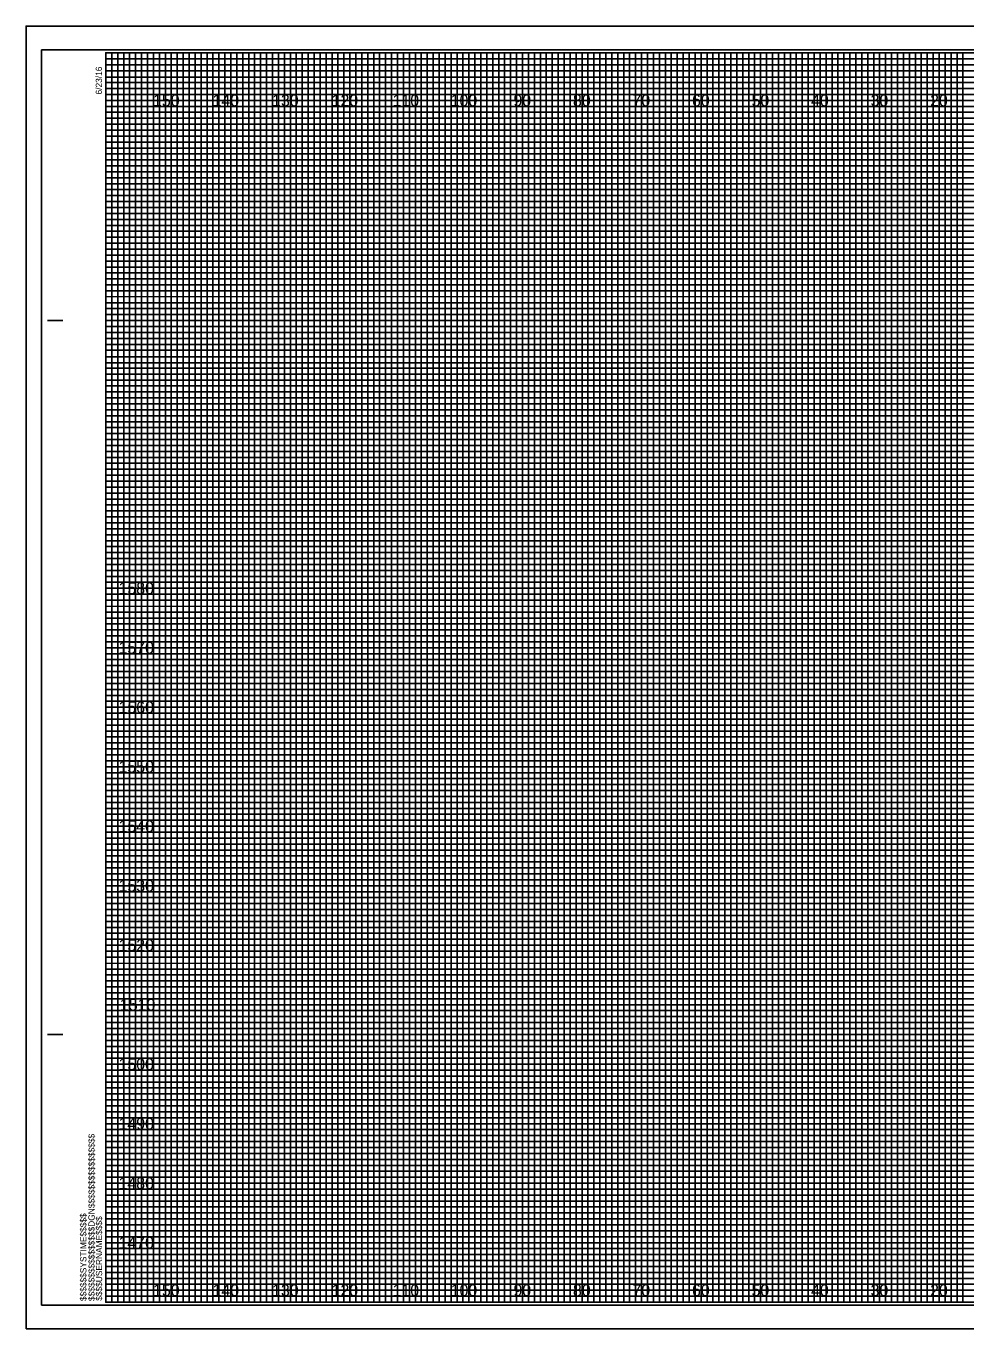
# Model space of a CAD drawing. Extents: x -13 to 323, y -5 to 215.
# Drawn here: x -13.4 to 144.5, y -4.5 to 214.5 of the extents above; entities that cross this region are included whole.
import ezdxf

# ---------------------------------------------------------------- set-up
doc = ezdxf.new("R2010")
doc.units = 0
for name, color, linetype in [('Exist Cross Section Cell', 7, 'Continuous'), ('Exist XS Center Line Elevation Label', 7, 'Continuous'), ('Exist XS Ground Line', 7, 'Continuous'), ('Prop XS Ditch Slope Text', 7, 'Continuous'), ('Prop XS EOT Tick Mark', 7, 'Continuous'), ('Prop XS Finish Grade Earthwork', 7, 'Continuous'), ('Prop XS Finish Grade Pavement', 7, 'Continuous'), ('Prop XS Pvmt Edge Slope', 7, 'Continuous'), ('Prop XS SE Text', 7, 'Continuous'), ('Prop XS Subgrade Earthwork', 7, 'Continuous'), ('Scratch_Level_5', 7, 'Continuous')]:
    doc.layers.add(name, color=color, linetype=linetype)

msp = doc.modelspace()

# ---------------------------------------------------------------- linework, layer by layer
at = {"layer": 'Exist Cross Section Cell'}
for points in [[(0, 210), (5, 210), (5, 0), (15, 0), (15, 210), (25, 210), (25, 0), (35, 0), (35, 210), (45, 210), (45, 0), (55, 0), (55, 210), (65, 210), (65, 0), (75, 0), (75, 210), (85, 210), (85, 0), (95, 0), (95, 210), (105, 210), (105, 0), (115, 0), (115, 210), (125, 210), (125, 0), (135, 0), (135, 210), (145, 210)], [(0, 205), (275, 205)], [(0, 185), (320, 185), (320, 195), (0, 195)], [(0, 165), (320, 165), (320, 175), (0, 175)], [(0, 145), (320, 145), (320, 155), (0, 155)], [(0, 125), (320, 125), (320, 135), (0, 135)], [(0, 105), (320, 105), (320, 115), (0, 115)], [(0, 85), (320, 85), (320, 95), (0, 95)], [(0, 65), (320, 65), (320, 75), (0, 75)], [(0, 45), (320, 45), (320, 55), (0, 55)], [(0, 25), (320, 25), (320, 35), (0, 35)], [(0, 5), (320, 5), (320, 15), (0, 15)]]:
    msp.add_lwpolyline(points, dxfattribs=at)
at = {"layer": 'Exist XS Center Line Elevation Label'}
for p, q in [((10, 210), (0, 210)), ((10, 0), (10, 210)), ((30, 210), (20, 210)), ((20, 210), (20, 0)), ((30, 0), (30, 210)), ((50, 210), (40, 210)), ((40, 210), (40, 0)), ((50, 0), (50, 210)), ((70, 210), (60, 210)), ((60, 210), (60, 0)), ((70, 0), (70, 210)), ((90, 210), (80, 210)), ((80, 210), (80, 0)), ((90, 0), (90, 210)), ((110, 210), (100, 210)), ((100, 210), (100, 0)), ((110, 0), (110, 210)), ((130, 210), (120, 210)), ((120, 210), (120, 0)), ((130, 0), (130, 210)), ((150, 210), (140, 210)), ((140, 210), (140, 0)), ((20, 0), (10, 0)), ((40, 0), (30, 0)), ((60, 0), (50, 0)), ((80, 0), (70, 0)), ((100, 0), (90, 0)), ((120, 0), (110, 0)), ((140, 0), (130, 0))]:
    msp.add_line(p, q, dxfattribs=at)
for points in [[(0, 200), (320, 200), (320, 190), (0, 190)], [(0, 180), (320, 180), (320, 170), (0, 170)], [(0, 160), (320, 160), (320, 150), (0, 150)], [(0, 140), (320, 140), (320, 130), (0, 130)], [(0, 120), (320, 120), (320, 110), (0, 110)], [(0, 100), (320, 100), (320, 90), (0, 90)], [(0, 80), (320, 80), (320, 70), (0, 70)], [(0, 60), (320, 60), (320, 50), (0, 50)], [(0, 40), (320, 40), (320, 30), (0, 30)], [(0, 20), (320, 20), (320, 10), (0, 10)]]:
    msp.add_lwpolyline(points, dxfattribs=at)
at = {"layer": 'Prop XS Ditch Slope Text'}
for p, q in [((323.3, 214.5), (-13.4, 214.5)), ((-13.4, 214.5), (-13.4, -4.5)), ((-13.4, -4.5), (323.3, -4.5))]:
    msp.add_line(p, q, dxfattribs=at)
at = {"layer": 'Prop XS EOT Tick Mark'}
msp.add_lwpolyline([(-10.8, -0.5), (322.4, -0.5), (322.4, 210.5), (-10.8, 210.5)], close=True, dxfattribs=at)
at = {"layer": 'Prop XS Finish Grade Earthwork'}
for p, q in [((10, 0), (10, 210)), ((20, 0), (20, 210)), ((30, 0), (30, 210)), ((40, 0), (40, 210)), ((50, 0), (50, 210)), ((60, 0), (60, 210)), ((70, 0), (70, 210)), ((80, 0), (80, 210)), ((90, 0), (90, 210)), ((100, 0), (100, 210)), ((110, 0), (110, 210)), ((120, 0), (120, 210)), ((130, 0), (130, 210)), ((140, 0), (140, 210)), ((0, 200), (320, 200)), ((0, 190), (320, 190)), ((0, 180), (320, 180)), ((0, 170), (320, 170)), ((0, 160), (320, 160)), ((0, 150), (320, 150)), ((0, 140), (320, 140)), ((0, 130), (320, 130)), ((0, 120), (320, 120)), ((0, 110), (320, 110)), ((0, 100), (320, 100)), ((0, 90), (320, 90)), ((0, 80), (320, 80)), ((0, 70), (320, 70)), ((0, 60), (320, 60)), ((0, 50), (320, 50)), ((0, 40), (320, 40)), ((0, 30), (320, 30)), ((0, 20), (320, 20)), ((0, 10), (320, 10))]:
    msp.add_line(p, q, dxfattribs=at)
at = {"layer": 'Prop XS Finish Grade Pavement'}
for p, q in [((-9.8, 165), (-7.3, 165)), ((-9.7, 165), (-7.2, 165)), ((-9.8, 45), (-7.3, 45)), ((-9.7, 45), (-7.2, 45)), ((0, 0), (0, 0)), ((0, 0), (0, 0)), ((0, 0), (0, 0)), ((0, 0), (0, 0)), ((0, 0), (0, 0)), ((0, 0), (0, 0)), ((0, 0), (0, 0))]:
    msp.add_line(p, q, dxfattribs=at)
msp.add_lwpolyline([(320, 210), (0, 210), (0, 0), (320, 0)], close=True, dxfattribs=at)
at = {"layer": 'Prop XS Pvmt Edge Slope'}
msp.add_lwpolyline([(-13.4, -4.5), (323.3, -4.5), (323.3, 214.5), (-13.4, 214.5)], close=True, dxfattribs=at)
at = {"layer": 'Prop XS Subgrade Earthwork'}
for points in [[(0, 0), (1, 0), (1, 210), (2, 210), (2, 0)], [(2, 0), (3, 0), (3, 210), (4, 210), (4, 0)], [(5, 0), (6, 0), (6, 210), (7, 210), (7, 0)], [(7, 0), (8, 0), (8, 210), (9, 210), (9, 0)], [(10, 0), (11, 0), (11, 210), (12, 210), (12, 0)], [(12, 0), (13, 0), (13, 210), (14, 210), (14, 0)], [(15, 0), (16, 0), (16, 210), (17, 210), (17, 0)], [(17, 0), (18, 0), (18, 210), (19, 210), (19, 0)], [(20, 0), (21, 0), (21, 210), (22, 210), (22, 0)], [(22, 0), (23, 0), (23, 210), (24, 210), (24, 0)], [(25, 0), (26, 0), (26, 210), (27, 210), (27, 0)], [(27, 0), (28, 0), (28, 210), (29, 210), (29, 0)], [(30, 0), (31, 0), (31, 210), (32, 210), (32, 0)], [(32, 0), (33, 0), (33, 210), (34, 210), (34, 0)], [(35, 0), (36, 0), (36, 210), (37, 210), (37, 0)], [(37, 0), (38, 0), (38, 210), (39, 210), (39, 0)], [(40, 0), (41, 0), (41, 210), (42, 210), (42, 0)], [(42, 0), (43, 0), (43, 210), (44, 210), (44, 0)], [(45, 0), (46, 0), (46, 210), (47, 210), (47, 0)], [(47, 0), (48, 0), (48, 210), (49, 210), (49, 0)], [(50, 0), (51, 0), (51, 210), (52, 210), (52, 0)], [(52, 0), (53, 0), (53, 210), (54, 210), (54, 0)], [(55, 0), (56, 0), (56, 210), (57, 210), (57, 0)], [(57, 0), (58, 0), (58, 210), (59, 210), (59, 0)], [(60, 0), (61, 0), (61, 210), (62, 210), (62, 0)], [(62, 0), (63, 0), (63, 210), (64, 210), (64, 0)], [(65, 0), (66, 0), (66, 210), (67, 210), (67, 0)], [(67, 0), (68, 0), (68, 210), (69, 210), (69, 0)], [(70, 0), (71, 0), (71, 210), (72, 210), (72, 0)], [(72, 0), (73, 0), (73, 210), (74, 210), (74, 0)], [(75, 0), (76, 0), (76, 210), (77, 210), (77, 0)], [(77, 0), (78, 0), (78, 210), (79, 210), (79, 0)], [(80, 0), (81, 0), (81, 210), (82, 210), (82, 0)], [(82, 0), (83, 0), (83, 210), (84, 210), (84, 0)], [(85, 0), (86, 0), (86, 210), (87, 210), (87, 0)], [(87, 0), (88, 0), (88, 210), (89, 210), (89, 0)], [(90, 0), (91, 0), (91, 210), (92, 210), (92, 0)], [(92, 0), (93, 0), (93, 210), (94, 210), (94, 0)], [(95, 0), (96, 0), (96, 210), (97, 210), (97, 0)], [(97, 0), (98, 0), (98, 210), (99, 210), (99, 0)], [(100, 0), (101, 0), (101, 210), (102, 210), (102, 0)], [(102, 0), (103, 0), (103, 210), (104, 210), (104, 0)], [(105, 0), (106, 0), (106, 210), (107, 210), (107, 0)], [(107, 0), (108, 0), (108, 210), (109, 210), (109, 0)], [(110, 0), (111, 0), (111, 210), (112, 210), (112, 0)], [(112, 0), (113, 0), (113, 210), (114, 210), (114, 0)], [(115, 0), (116, 0), (116, 210), (117, 210), (117, 0)], [(117, 0), (118, 0), (118, 210), (119, 210), (119, 0)], [(120, 0), (121, 0), (121, 210), (122, 210), (122, 0)], [(122, 0), (123, 0), (123, 210), (124, 210), (124, 0)], [(125, 0), (126, 0), (126, 210), (127, 210), (127, 0)], [(127, 0), (128, 0), (128, 210), (129, 210), (129, 0)], [(130, 0), (131, 0), (131, 210), (132, 210), (132, 0)], [(132, 0), (133, 0), (133, 210), (134, 210), (134, 0)], [(135, 0), (136, 0), (136, 210), (137, 210), (137, 0)], [(137, 0), (138, 0), (138, 210), (139, 210), (139, 0)], [(140, 0), (141, 0), (141, 210), (142, 210), (142, 0)], [(142, 0), (143, 0), (143, 210), (144, 210), (144, 0)]]:
    msp.add_lwpolyline(points, dxfattribs=at)
at = {"layer": 'Scratch_Level_5'}
for p, q in [((0, 209), (260, 209)), ((260, 207.98), (0, 207.98)), ((0, 207.98), (0, 207)), ((0, 207), (260, 207)), ((260, 205.89), (0, 205.89)), ((0, 205.89), (0, 204)), ((0, 204), (320, 204))]:
    msp.add_line(p, q, dxfattribs=at)
for points in [[(0, 203), (270, 203), (320, 203), (320, 202), (0, 202)], [(0, 201), (320, 201), (320, 199), (0, 199)], [(0, 198), (320, 198), (320, 197), (0, 196.98)], [(0, 196), (320, 196), (320, 194), (0, 194)], [(0, 193), (320, 193), (320, 192), (0, 192)], [(0, 191), (320, 191), (320, 189), (0, 189)], [(0, 188), (320, 188), (320, 187), (0, 187)], [(0, 186), (320, 186), (320, 184), (0, 184)], [(0, 183), (320, 183), (320, 182), (0, 182)], [(0, 181), (320, 181), (320, 179), (0, 179)], [(0, 178), (320, 178), (320, 177), (0, 177)], [(0, 176), (320, 176), (320, 173.95), (320, 173), (320, 172), (0, 172)], [(0, 174), (320, 174), (320, 173), (0, 173)], [(0, 171), (320, 171), (320, 169), (0, 169.03)], [(0, 169.03), (320, 169), (320, 168), (0, 168)], [(0, 167), (320, 167), (320, 166), (0, 166)], [(0, 164), (320, 164), (320, 163), (0, 163)], [(0, 162), (320, 162), (320, 161), (0, 161)], [(-0.07, 158.89), (320, 158.89), (320, 157.88), (-0.07, 157.88)], [(0, 157), (320, 157), (320, 156), (0, 156)], [(0, 154), (320, 154), (320, 153), (0, 153)], [(0, 152), (320, 152), (320, 151), (0, 151)], [(0, 149), (320, 149), (320, 148), (0, 148)], [(0, 147), (320, 147), (320, 146), (0, 146)], [(0, 144), (320, 144), (320, 143), (0, 143)], [(0, 142), (320, 142), (320, 141), (0, 141)], [(0, 139), (320, 139), (319.99, 137.98), (0, 138)], [(0, 137), (320, 137), (320, 136), (0, 136)], [(0, 134), (320, 134), (320, 133), (0, 133)], [(0, 132), (320, 132), (320, 131), (0, 131)], [(0, 129), (320, 129), (320, 128), (0, 128)], [(0, 127), (320, 127), (320, 126), (0, 126)], [(0, 124), (320, 124), (320, 123), (0, 123)], [(0, 122), (320, 122), (320, 121), (0, 121)], [(0, 119), (320, 119), (320, 118), (0, 118)], [(0, 116.99), (320.07, 116.91), (320, 116), (0, 116)], [(0, 114), (320, 114), (320, 113), (0, 113)], [(0, 112), (320, 112), (320, 111), (0, 111)], [(0, 109), (320, 109), (320, 108), (0, 108)], [(0, 107), (320, 107), (320, 106), (0, 106)], [(0, 104), (320, 104), (320, 103), (0, 103)], [(0, 102), (320, 102), (320, 101), (0, 101)], [(0, 99), (320, 99), (320, 98), (0, 98)], [(0, 97), (320, 97), (320, 96), (0, 96)], [(0, 94), (320, 94), (320, 93), (0, 93)], [(0, 92), (320, 92), (320, 91), (0, 91)], [(0, 89), (320, 89), (320, 88), (0, 88)], [(0, 87), (320, 87), (320, 86), (0, 86)], [(0, 84), (320, 84), (320, 83), (0, 83)], [(0, 82), (320, 82), (320, 81), (0, 81)], [(0, 79), (320, 79), (319.99, 77.98), (0, 78)], [(0, 77), (320, 77), (320, 76), (0, 76)], [(0, 74), (320, 74), (320, 73), (0, 73)], [(0, 72), (320, 72), (320, 71), (0, 71)], [(0, 69), (320, 69), (320, 68), (0, 68)], [(0, 67), (320, 67), (320, 66), (0, 66)], [(0, 64), (320, 64), (320, 63), (0, 63)], [(0, 62), (320, 62), (320, 61), (0, 61)], [(0, 59), (320, 59), (320, 58), (0, 58)], [(0, 56.99), (320.07, 56.91), (320, 56), (0, 56)], [(0, 54), (320, 54), (320, 53), (0, 53)], [(0, 52), (320, 52), (320, 51), (0, 51)], [(0, 49), (320, 49), (320, 48), (0, 48)], [(0, 47), (320, 47), (320, 46), (0, 46)], [(0, 44), (320, 44), (320, 43), (0, 43)], [(0, 42), (320, 42), (320, 41), (0, 41)], [(0, 39), (320, 39), (320, 38), (0, 38)], [(0, 37), (320, 37), (320, 36), (0, 36)], [(0, 34), (320, 34), (320, 33), (0, 33)], [(0, 32), (320, 32), (320, 31), (0, 31)], [(0, 29), (320, 29), (320, 28), (0, 28)], [(0, 27), (320, 27), (320, 26), (0, 26)], [(0, 24), (320, 24), (320, 23), (0, 23)], [(0, 22), (320, 22), (320, 21), (0, 21)], [(0, 19), (320, 19), (320, 18), (0, 18)], [(0, 17), (320, 17), (320, 16), (0, 16)], [(0, 14), (320, 14), (320, 13), (0, 13)], [(0, 12), (320, 12), (320, 11), (0, 11)], [(0, 9), (320, 9), (320, 8), (0, 8)], [(0, 7), (320, 7), (320, 6), (0, 6)], [(0, 4), (320, 4), (320, 3), (0, 3)], [(0, 2), (320, 2), (320, 1), (0, 1)]]:
    msp.add_lwpolyline(points, dxfattribs=at)

# ---------------------------------------------------------------- texts
at = {"layer": 'Exist XS Ground Line'}
for s, p in [('150', (7.93, 201)), ('140', (17.93, 201)), ('130', (27.93, 201)), ('120', (37.93, 201)), ('110', (48.17, 201)), ('100', (57.93, 201)), ('90', (68.48, 201)), ('80', (78.48, 201)), ('70', (88.48, 201)), ('60', (98.48, 201)), ('50', (108.48, 201)), ('40', (118.48, 201)), ('30', (128.48, 201)), ('20', (138.48, 201)), ('150', (7.93, 1)), ('140', (17.93, 1)), ('130', (27.93, 1)), ('120', (37.93, 1)), ('110', (48.17, 1)), ('100', (57.93, 1)), ('90', (68.48, 1)), ('80', (78.48, 1)), ('70', (88.48, 1)), ('60', (98.48, 1)), ('50', (108.48, 1)), ('40', (118.48, 1)), ('30', (128.48, 1)), ('20', (138.48, 1))]:
    msp.add_text(s, height=2, dxfattribs=at).set_placement(p)
at = {"layer": 'Prop XS Finish Grade Pavement'}
for s, p in [('6/23/16', (-0.65, 203)), ('$$$$$$$$$$$$$$$$DGN$$$$$$$$$$$$$$$$', (-1.88, 0.18)), ('$$$$$$SYSTIME$$$$$', (-3.26, 0.18)), ('$$$$USERNAME$$$$', (-0.62, 0.23))]:
    msp.add_text(s, height=1.05, rotation=90, dxfattribs=at).set_placement(p)
at = {"layer": 'Prop XS SE Text'}
for s, p in [('1580', (2.13, 119)), ('1570', (2.13, 109)), ('1560', (2.13, 99)), ('1550', (2.13, 89)), ('1540', (2.13, 79)), ('1530', (2.13, 69)), ('1520', (2.13, 59)), ('1510', (2.37, 49)), ('1500', (2.13, 39)), ('1490', (2.13, 29)), ('1480', (2.13, 19)), ('1470', (2.13, 9))]:
    msp.add_text(s, height=2, dxfattribs=at).set_placement(p)

doc.saveas('drawing.dxf')
